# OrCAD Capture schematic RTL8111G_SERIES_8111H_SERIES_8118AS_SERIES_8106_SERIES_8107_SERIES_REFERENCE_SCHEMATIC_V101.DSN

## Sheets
1 P06. Change Note: title: RTL81Gseries_81Hseries_8118ASseries_8106series_8107series 32 Pin Reference Schematic: Change Note; rev: A1; company: Realtek Semiconductor Corp.; note: RTL81Gseries_81Hseries_8118ASseries_8106series_8107series 32 Pin Reference Schematic; note: No.2, Innovation Road II, Hsinchu Science Park, Hsinchu 300, Taiwan
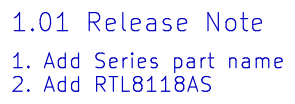
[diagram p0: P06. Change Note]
2 P01. Index: title: RTL81Gseries_81Hseries_8118ASseries_8106series_8107series 32 Pin Reference Schematic: Index
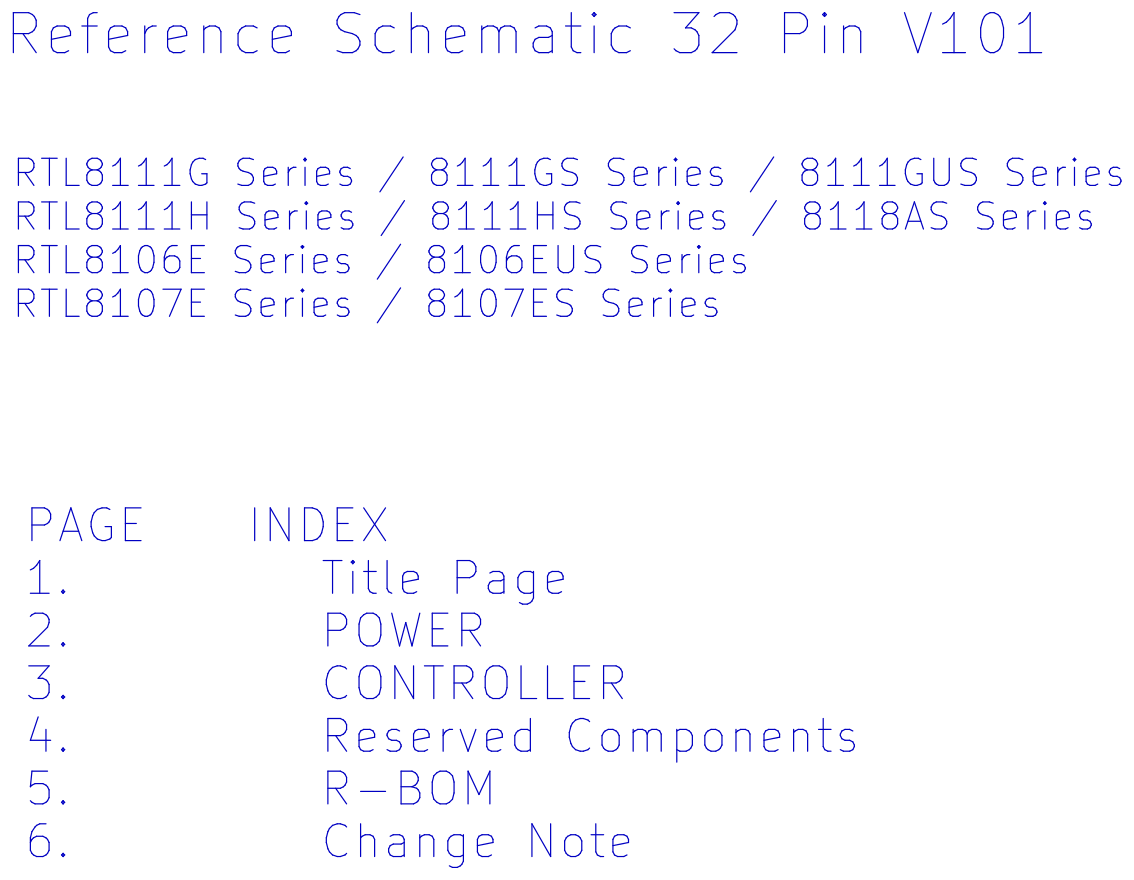
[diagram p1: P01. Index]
3 P02. POWER: size A3; title: RTL81Gseries_81Hseries_8118ASseries_8106series_8107series 32 Pin Reference Schematic : Power
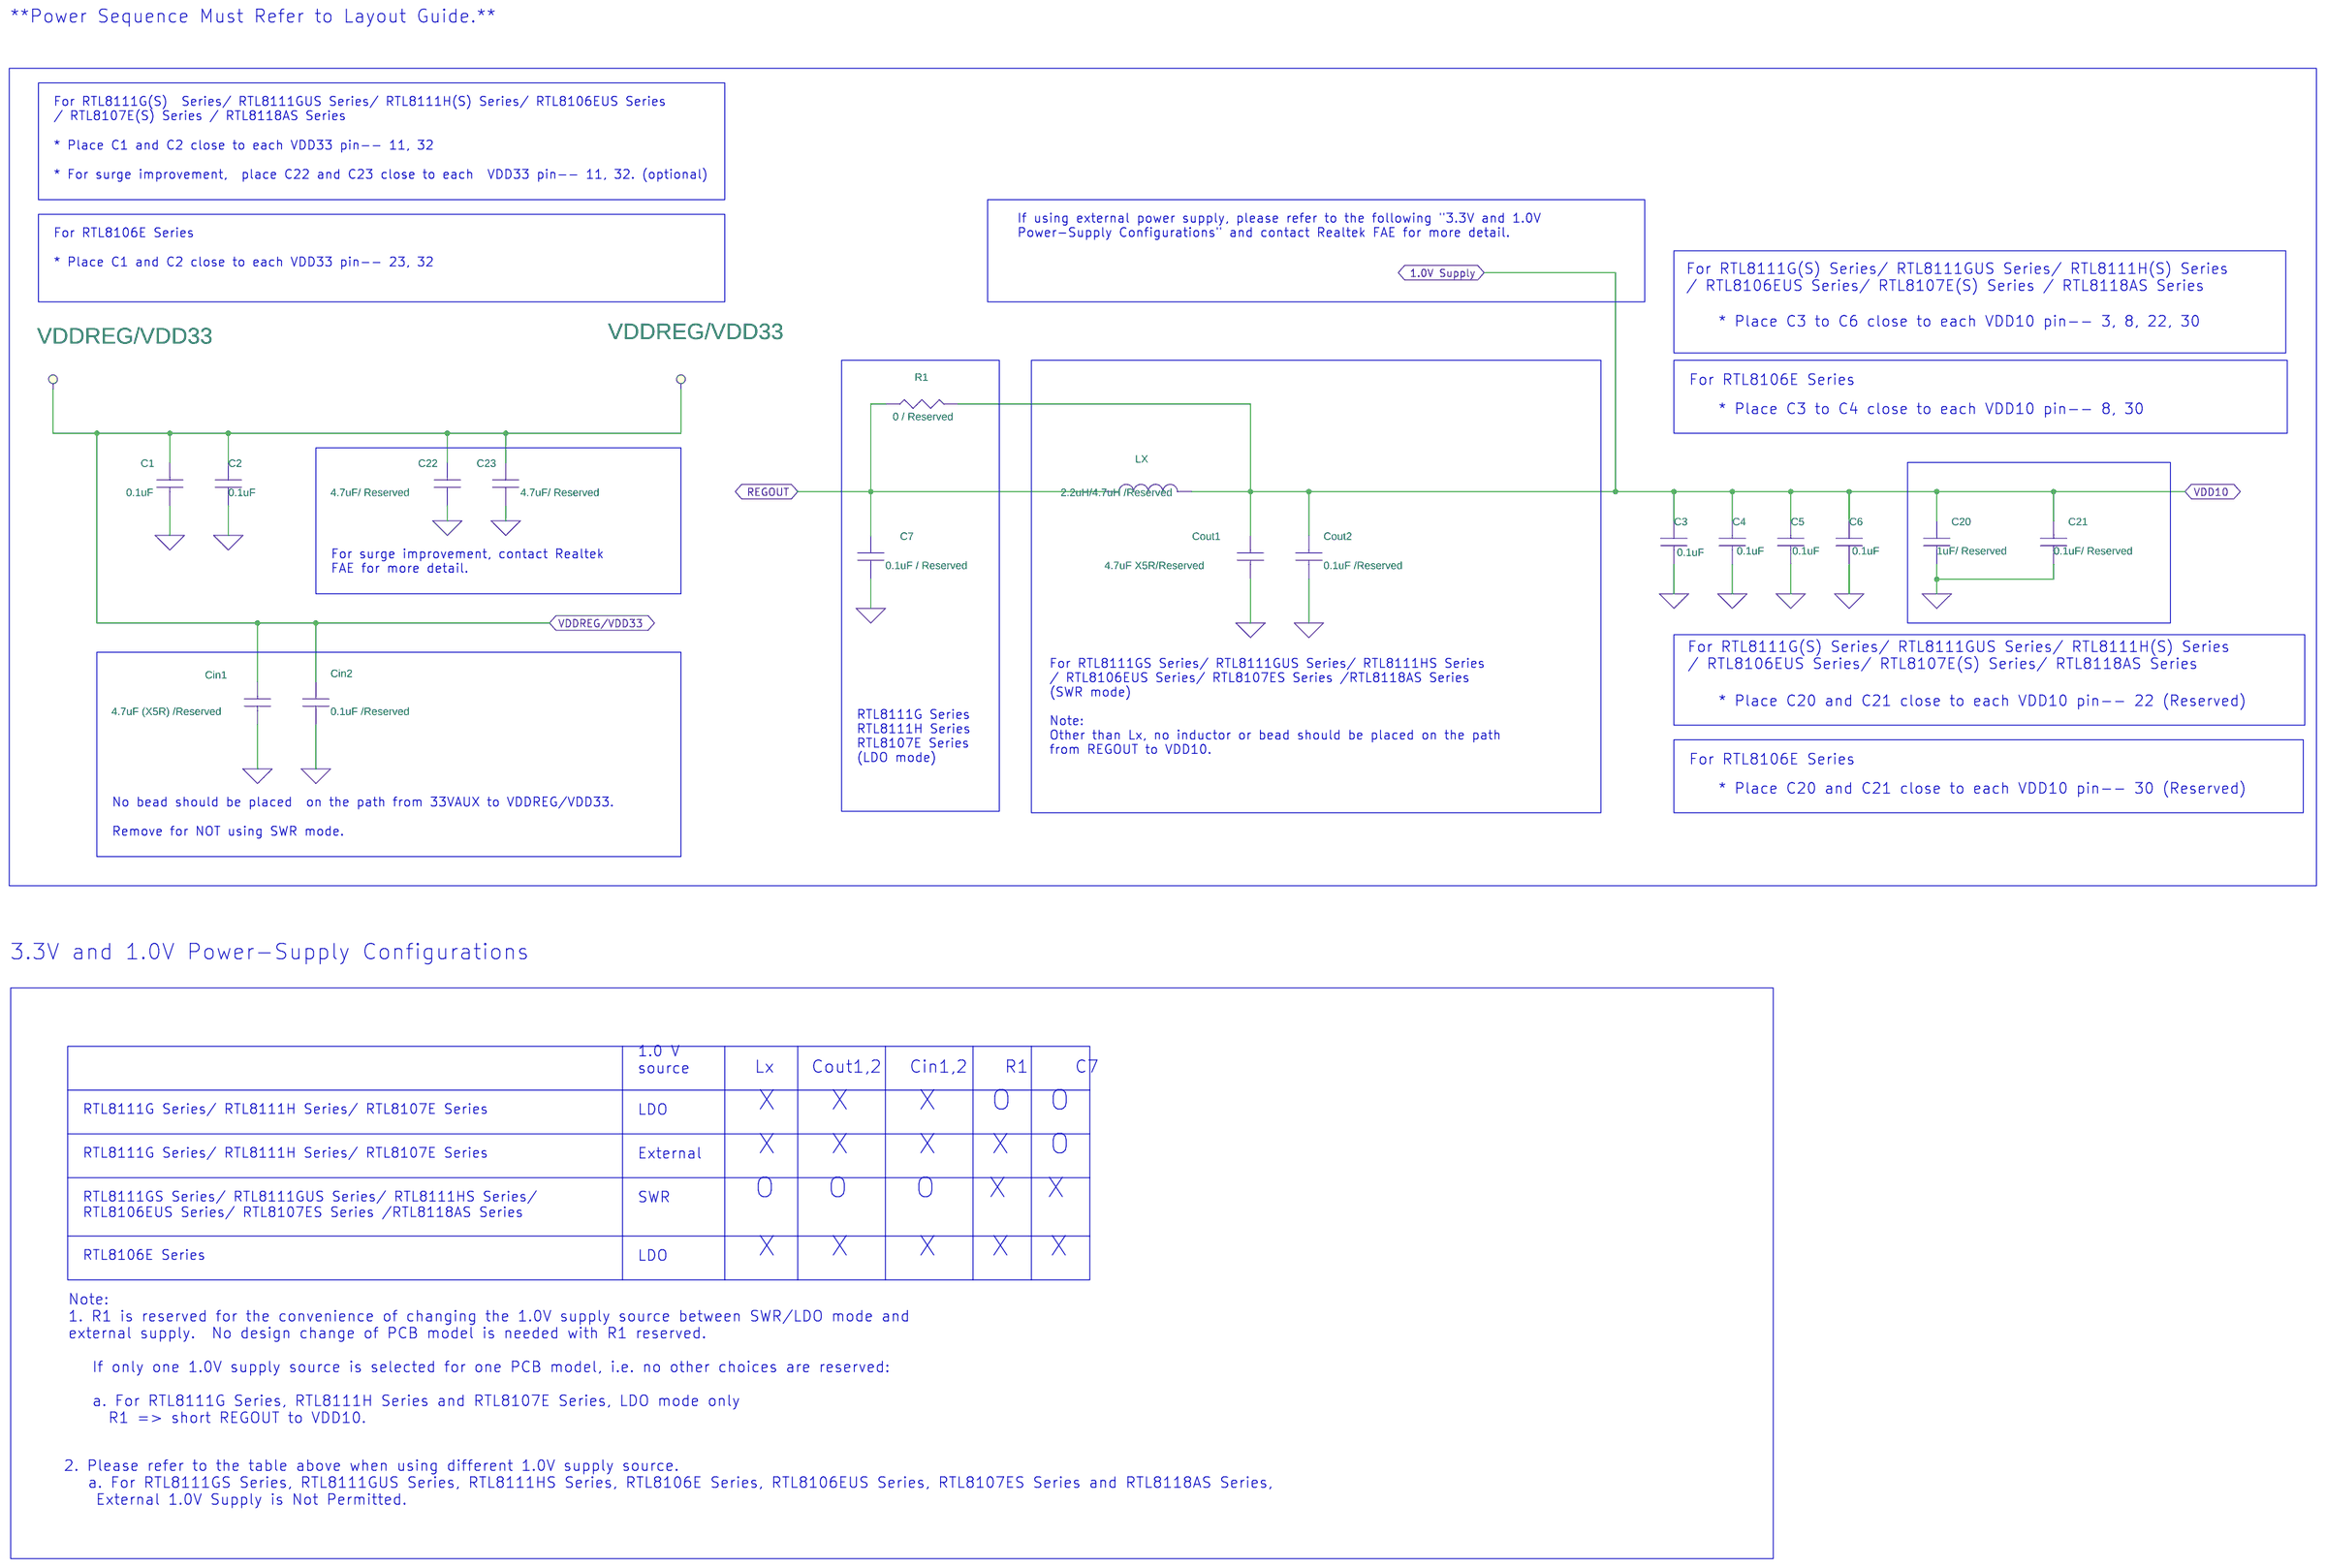
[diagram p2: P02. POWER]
4 P03. CONTROLLER: size A3; title: RTL81Gseries_81Hseries_8118ASseries_8106series_8107series 32 Pin Reference Schematic: Controller
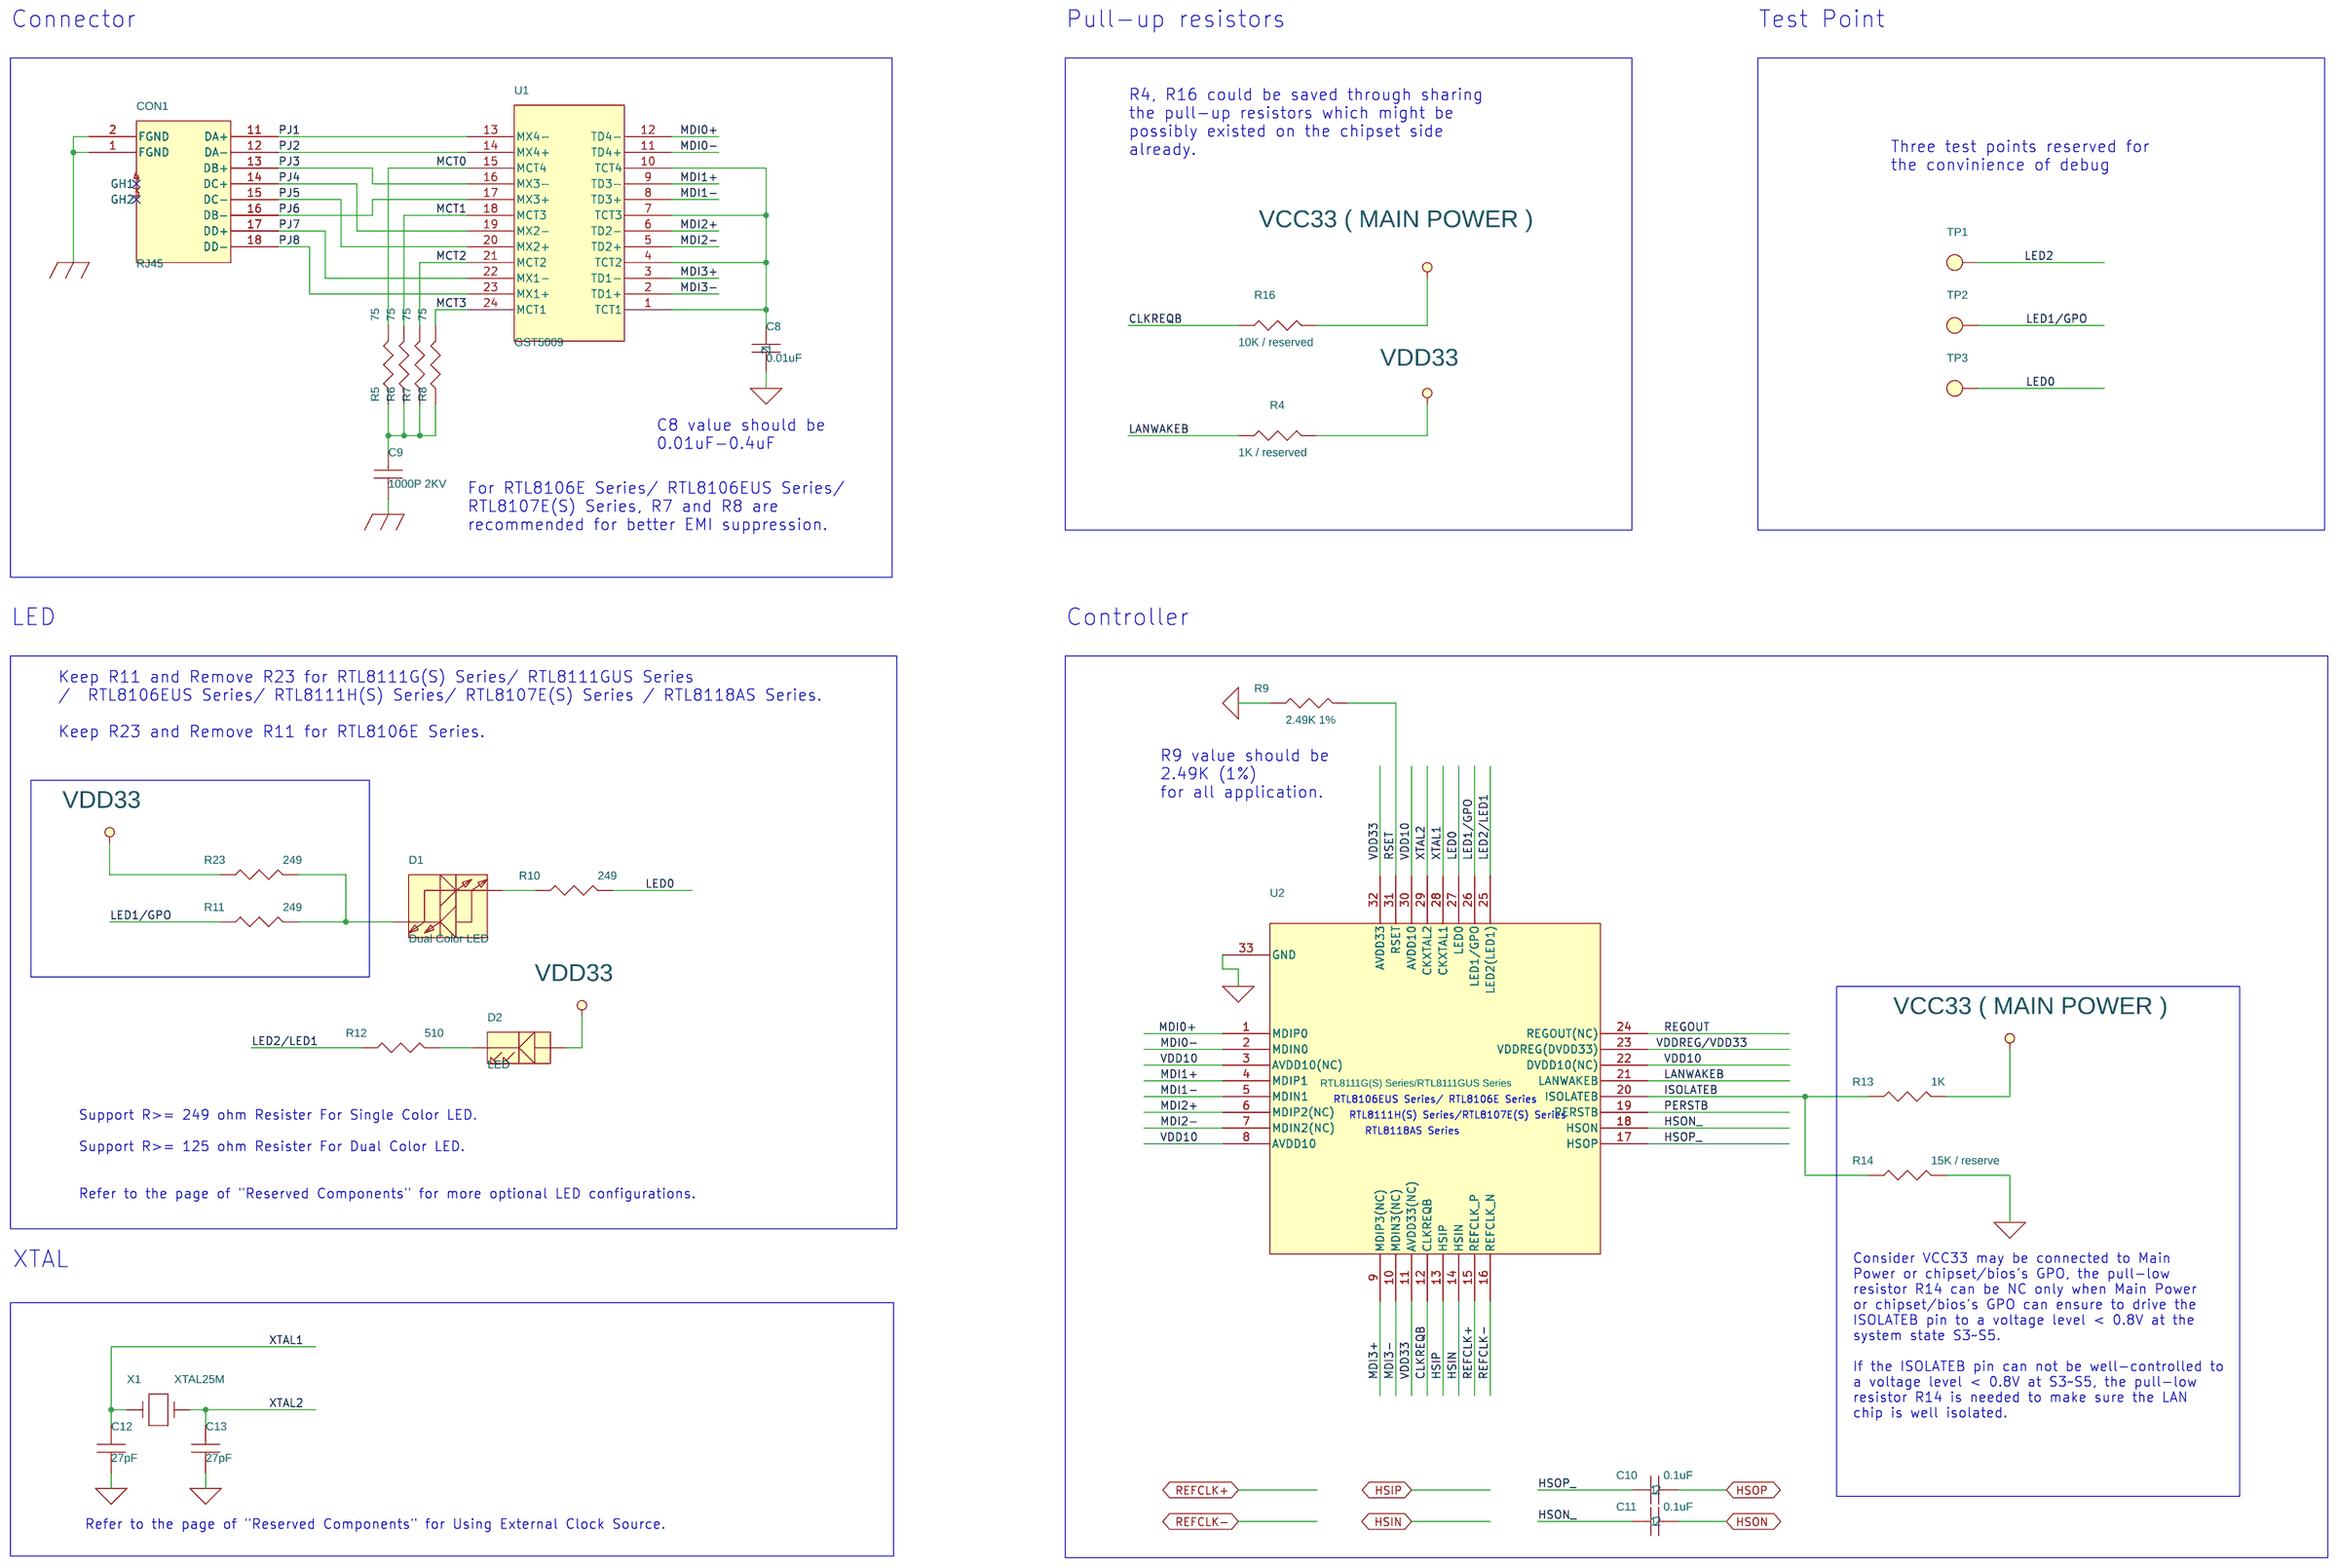
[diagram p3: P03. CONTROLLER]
5 P04. Reserved Components: size A3; title: RTL81Gseries_81Hseries_8118ASseries_8106series_8107series 32 Pin Reference Schematic:Reserved Components
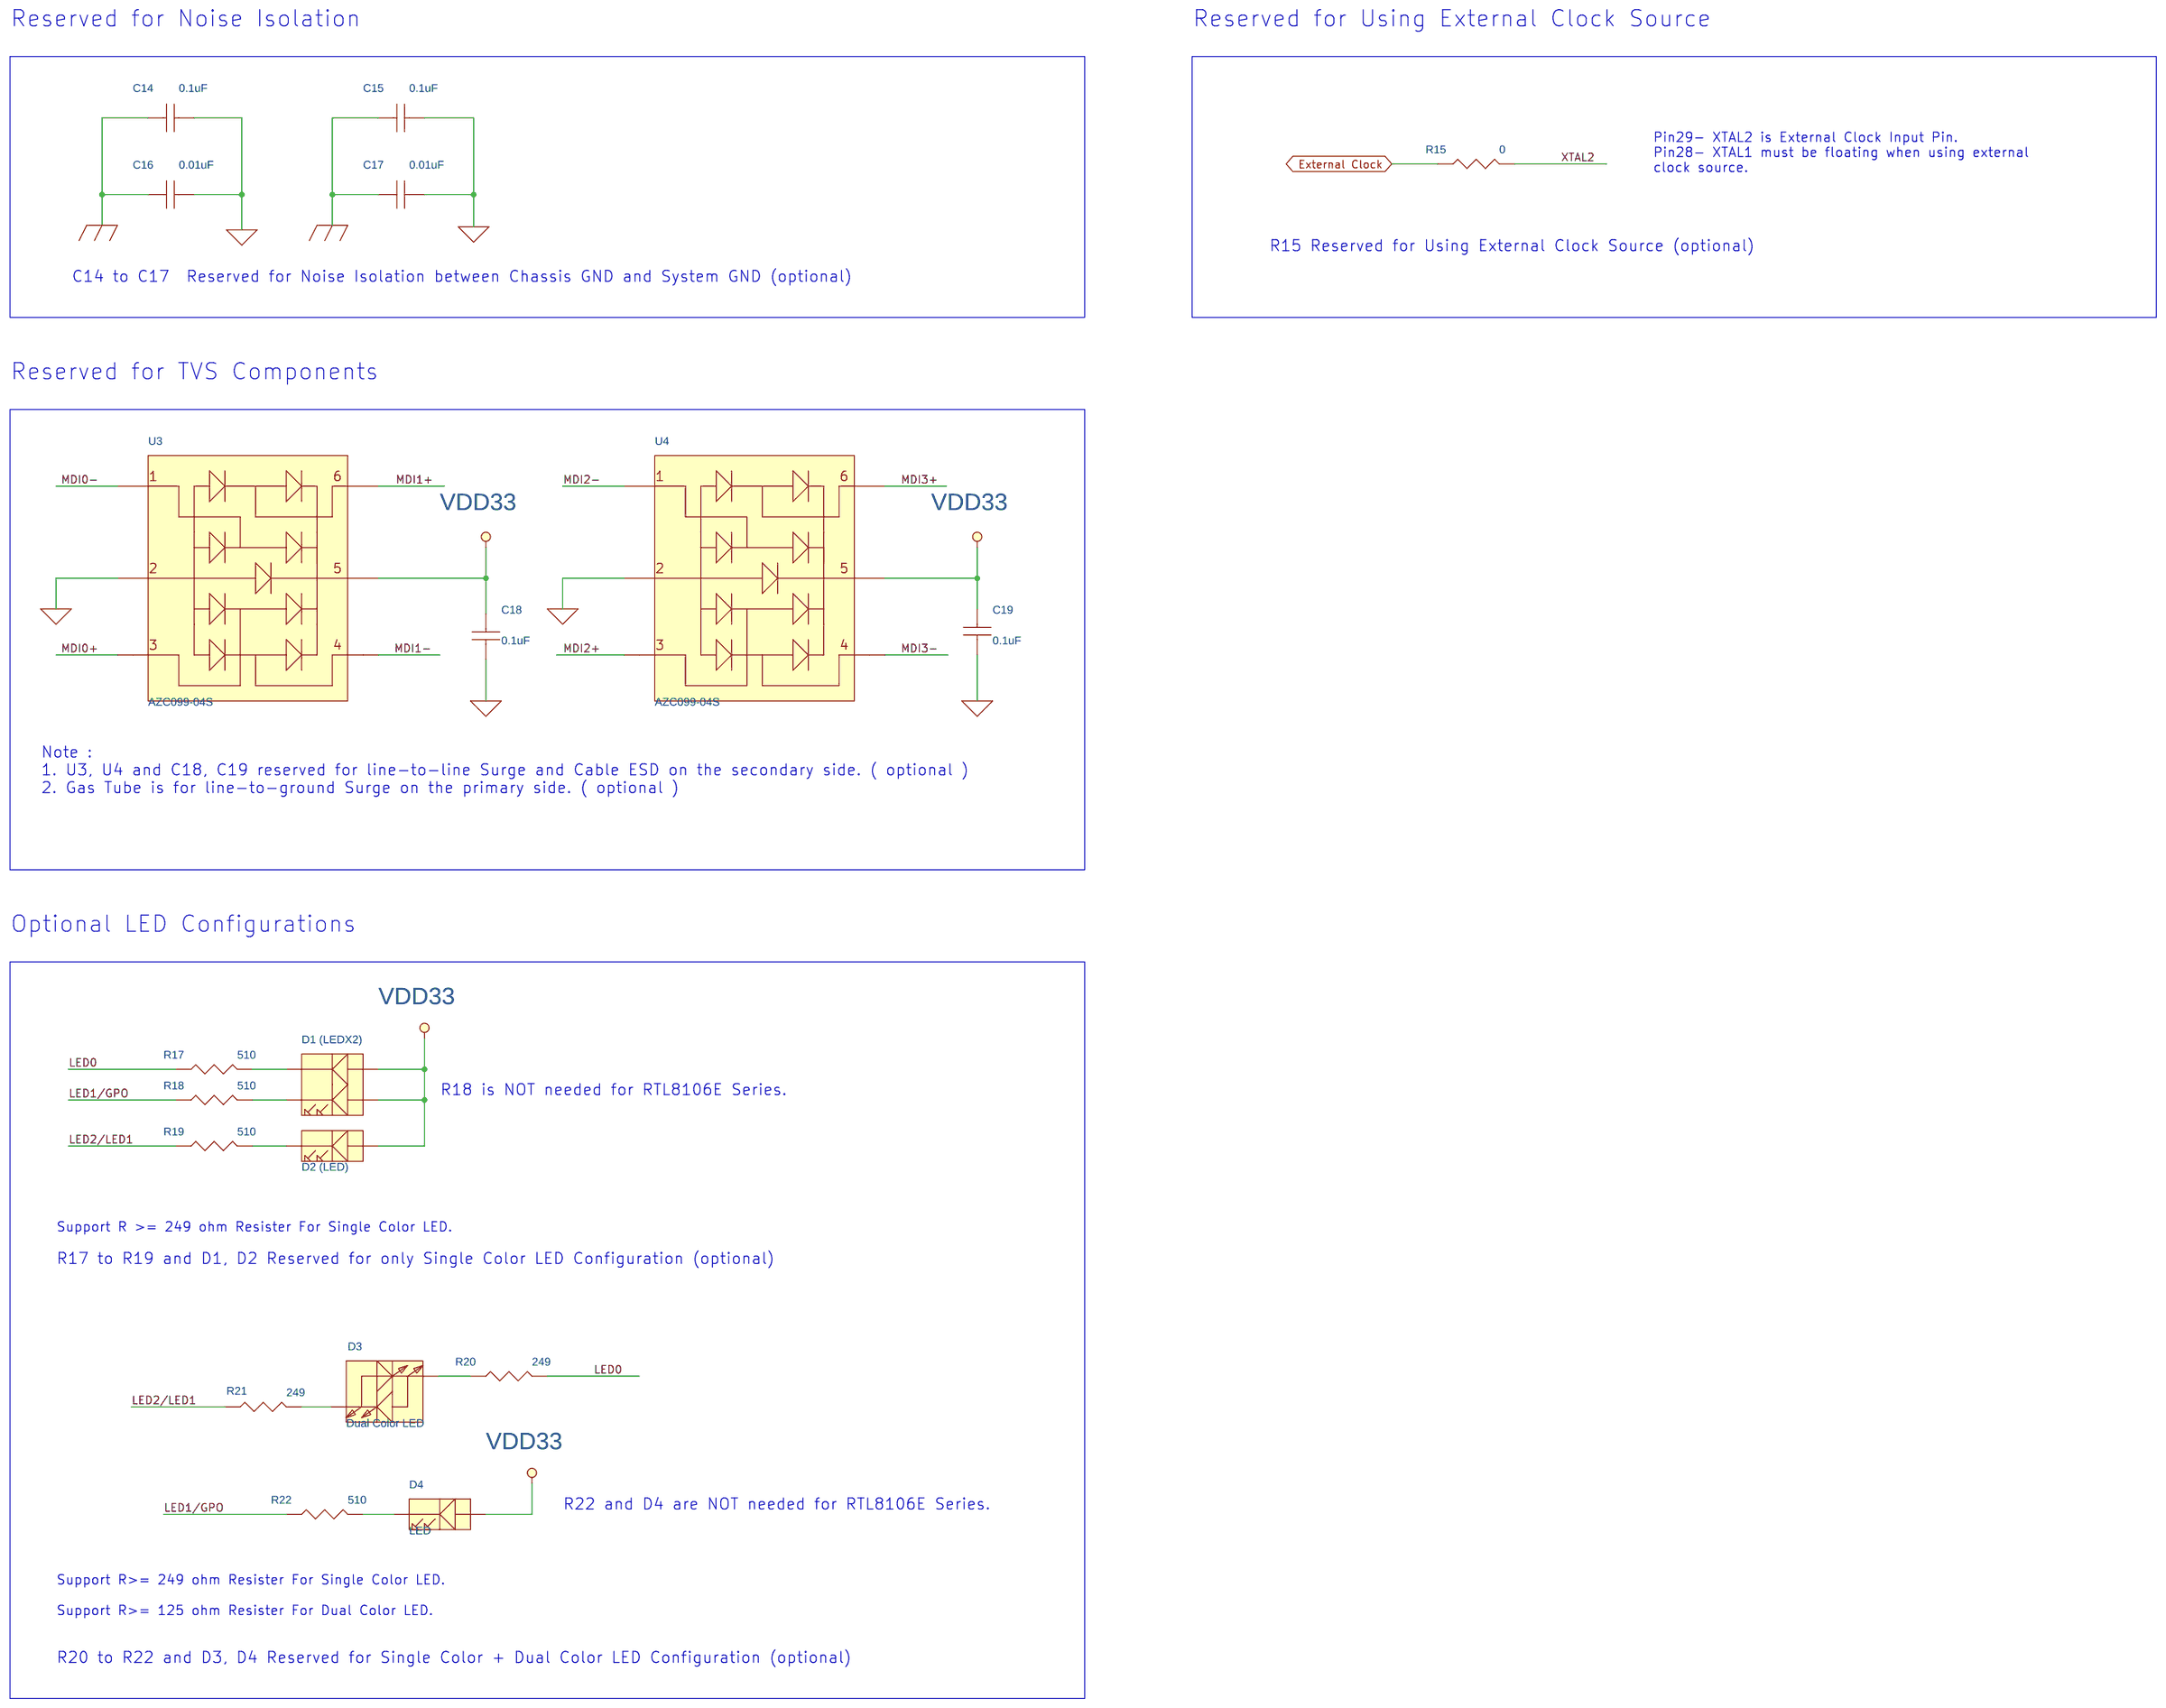
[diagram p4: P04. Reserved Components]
6 P05. R-BOM: title: RTL81Gseries_81Hseries_8118ASseries_8106series_8107series 32 Pin Reference Schematic: Bill of Materials
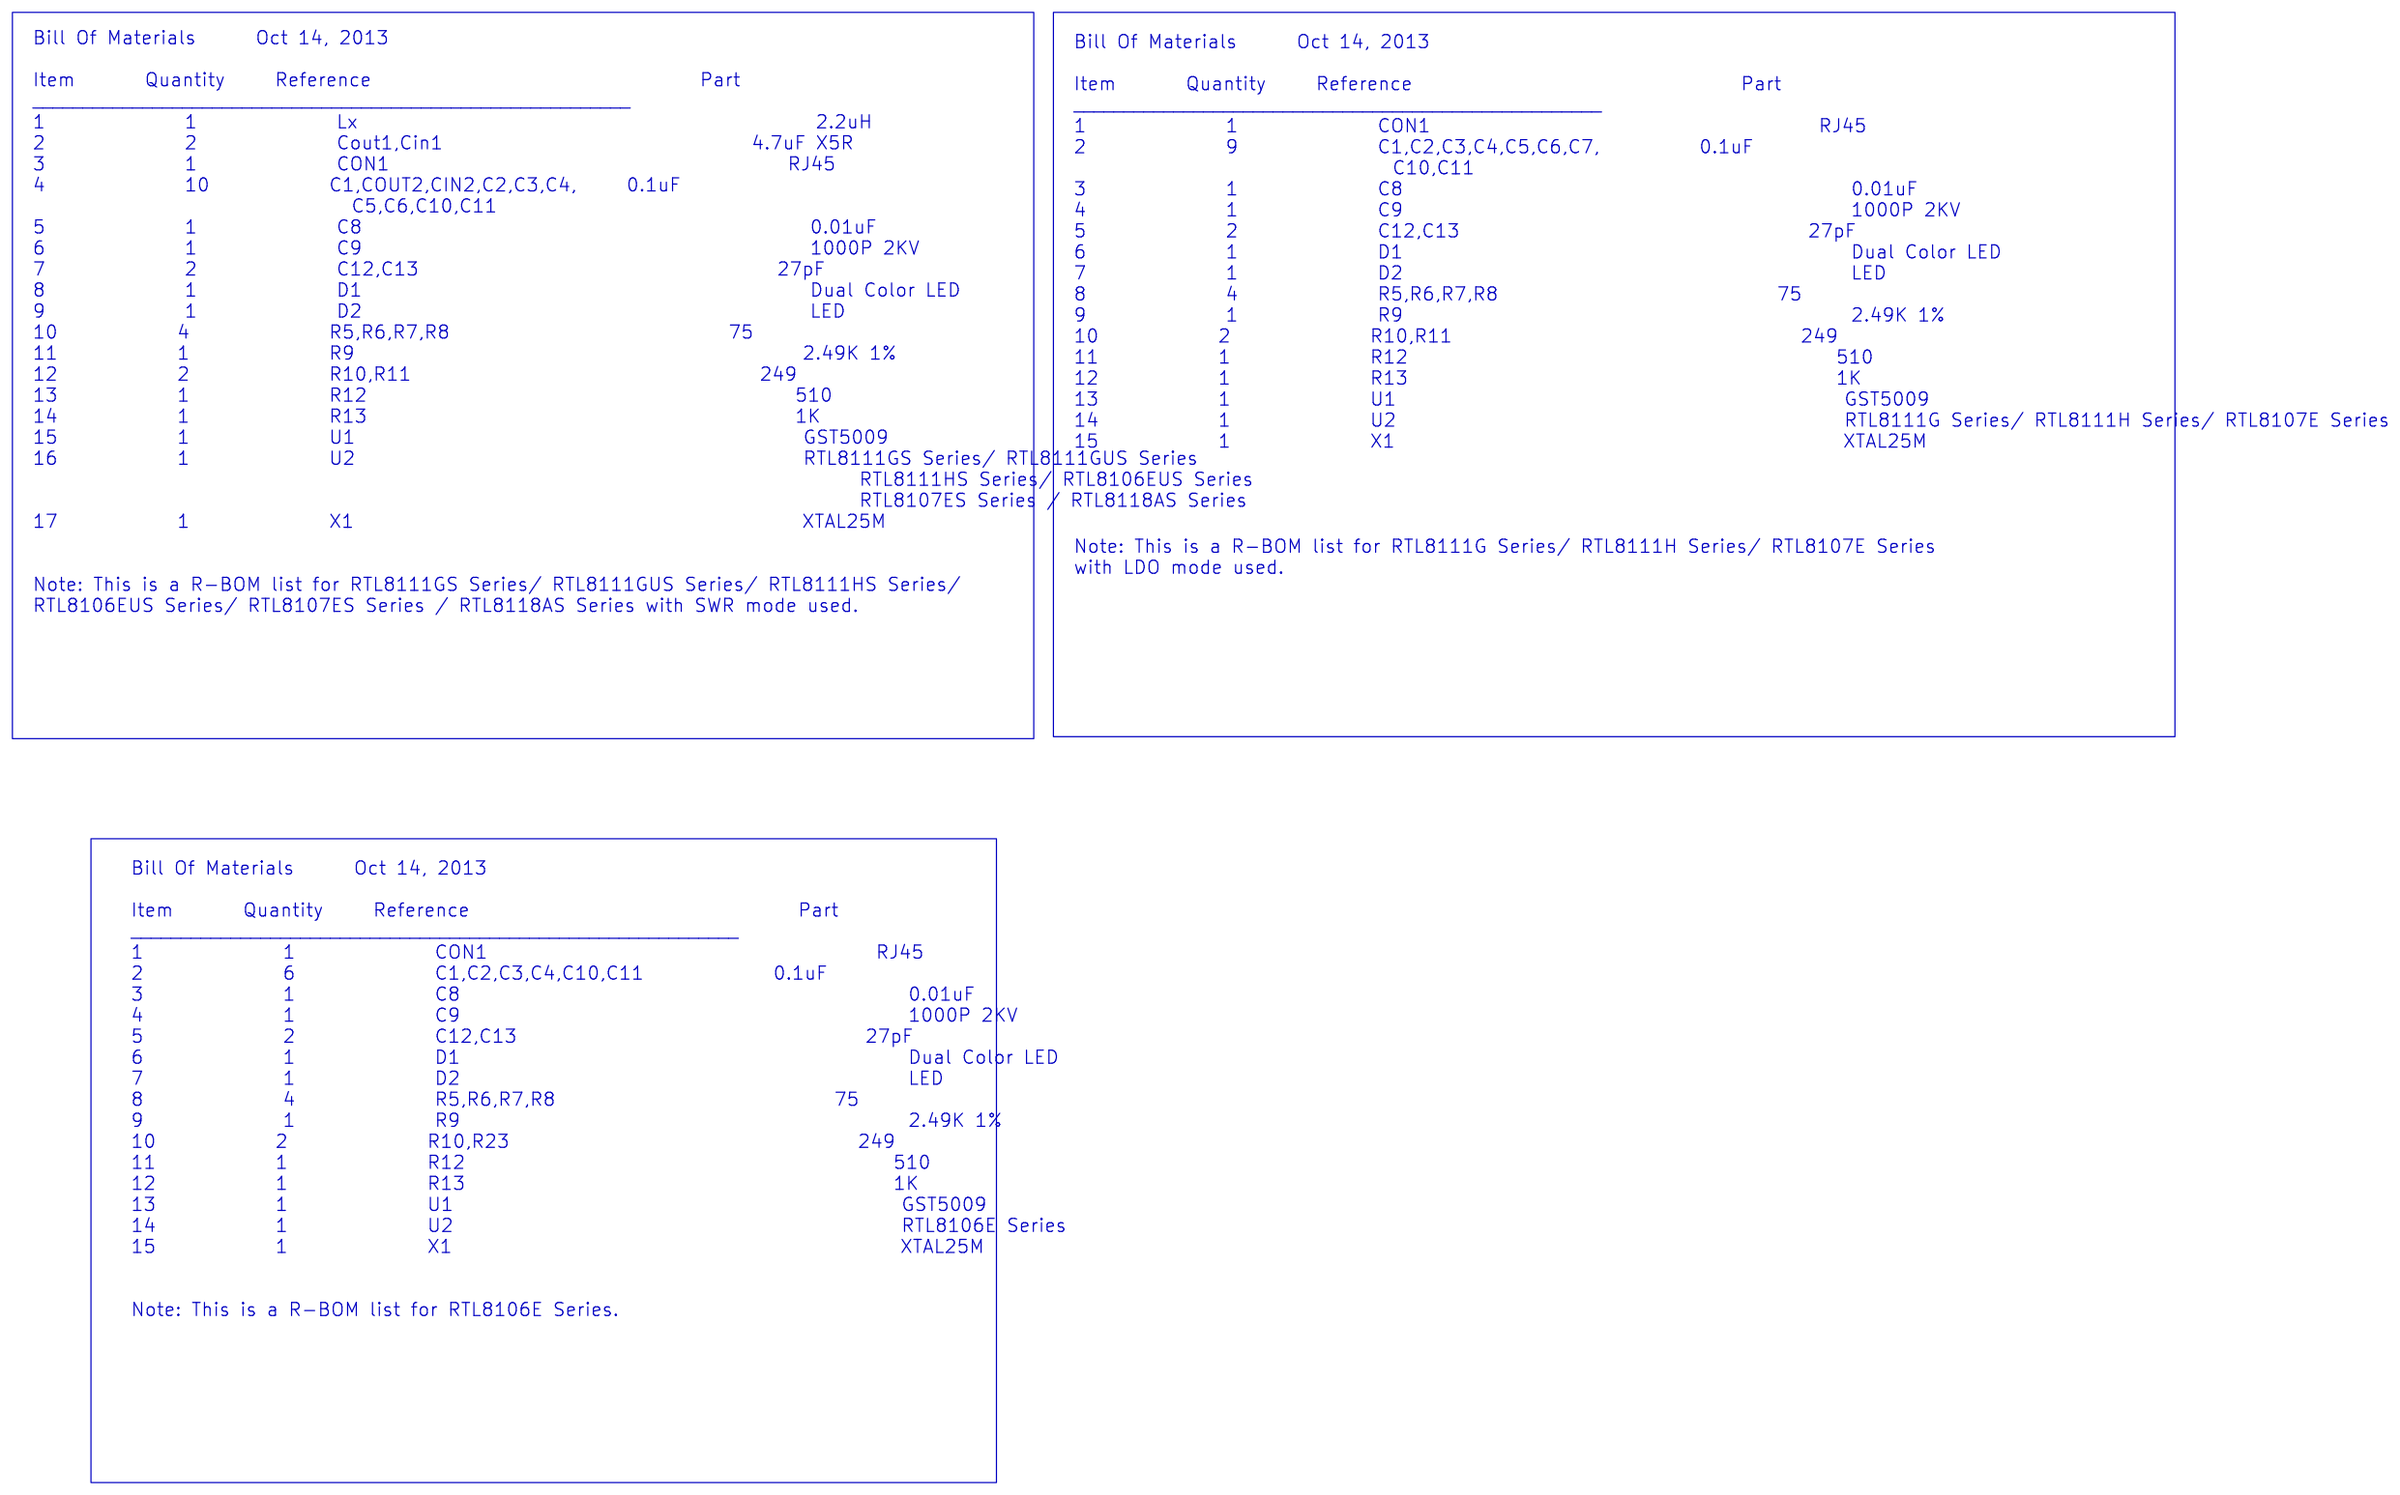
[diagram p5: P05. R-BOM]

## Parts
sheet P02. POWER
C1  0.1uF  [C0402C]
C2  0.1uF  [C0402C]
C3  0.1uF  [C0402C]
C4  0.1uF  [C0402C]
C5  0.1uF  [C0402C]
C6  0.1uF  [C0402C]
C7  0.1uF / Reserved  [C0402C]
C20  1uF/ Reserved  [C0402C]
C21  0.1uF/ Reserved  [C0402C]
C22  4.7uF/ Reserved  [C1206C]
C23  4.7uF/ Reserved  [C1206C]
Cin1  4.7uF (X5R) /Reserved  [C1206C]
Cin2  0.1uF /Reserved  [C0402C]
Cout1  4.7uF X5R/Reserved  [C0805C]
Cout2  0.1uF /Reserved  [C0402C]
LX  2.2uH/4.7uH /Reserved  [L\5X5\3.15]
R1  0 / Reserved  [R0603R]
sheet P03. CONTROLLER
C8  0.01uF  [C0402C]
C9  1000P 2KV  [C1206C]
C10  0.1uF
C11  0.1uF
C12  27pF  [C0402C]
C13  27pF  [C0402C]
CON1  RJ45  [RJ45S1X1]
D1  Dual Color LED  [LED2X2]
D2  LED  [LED]
R4  1K / reserved  [R0402R]
R5  75  [R0402R]
R6  75  [R0402R]
R7  75  [R0402R]
R8  75  [R0402R]
R9  2.49K 1%  [R0402R]
R10  249  [R0402R]
R11  249  [R0402R]
R12  510  [R0402R]
R13  1K  [R0402R]
R14  15K / reserve  [R0402R]
R16  10K / reserved  [R0402R]
R23  249  [R0402R]
TP1  TEST POINT
TP2  TEST POINT
TP3  TEST POINT
U1  GST5009  [GST5009-LFE9249-R]
U2  RTL8111G(S) Series/RTL8111GUS Series  [QFN6x6-48]
X1  XTAL25M  [XTAL]
sheet P04. Reserved Components
C14  0.1uF  [C0402C]
C15  0.1uF  [C0402C]
C16  0.01uF  [C0402C]
C17  0.01uF  [C0402C]
C18  0.1uF  [C0402C]
C19  0.1uF  [C0402C]
D1 (LEDX2)  LEDx2  [LED2X2]
D2 (LED)  LED  [LED]
D3  Dual Color LED  [LED2X2]
D4  LED  [LED]
R15  0  [R0402R]
R17  510  [R0402R]
R18  510  [R0402R]
R19  510  [R0402R]
R20  249  [R0402R]
R21  249  [R0402R]
R22  510  [R0402R]
U3  AZC099-04S  [SOT23-6L]
U4  AZC099-04S  [SOT23-6L]

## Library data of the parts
C1 = CAPACITOR_NON-POL_0: ROOM: 33vaux
C2 C9 C12-C17 C22 C23 Cin1 Cin2 = CAPACITOR_NON-POL_0
C3-C5 = CAPACITOR_NON-POL_0: ROOM: c_15
C6 C7 C20 C21 Cout1 Cout2 = CAPACITOR_NON-POL_0: ROOM: vdd18
LX = INDUCTOR_0: ROOM: vdd18
R1 R4-R23 = R
C8 = CAP_NP
C10 = CAP_NP_2
C11 C18 C19 = CAP_NP_1
CON1 = RJ45_2
D1 D3 = LED_2
D2 D2 (LED) D4 = LED_3
TP1-TP3 = TEST_POINT
U1 = H5007
U2 = RL5877_66
X1 = CRYSTAL_0
D1 (LEDX2) = LED_1
U3 U4 = 9346_5

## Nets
1.0V Supply: C3.1 C4.1 C5.1 C6.1 C20.1 C21.1 Cout1.1 Cout2.1 LX.2 R1.2
DGND: C1.2 C2.2 C3.2 C4.2 C5.2 C6.2 C7.2 C8.2 C12.2 C13.2 C14.2 C15.2 C16.2 C17.2 C18.2 C19.2 C20.2 C21.2 C22.2 C23.2 Cin1.2 Cin2.2 Cout1.2 Cout2.2 R9.1 R14.2 U2.33(GND) U3.2 U4.2
VCC33 ( Main Power ): R13.2 R16.2
VDD10: U2.3(AVDD10(NC)) U2.8(AVDD10) U2.22(DVDD10(NC)) U2.30(AVDD10)
VDD33: C1.1 C2.1 C18.1 C19.1 C22.1 C23.1 Cin1.1 Cin2.1 D1 (LEDX2).1 D1 (LEDX2).2 D2.1 D2 (LED).1 D4.1 R4.2 R23.1 U2.11(AVDD33(NC)) U2.32(AVDD33) U3.5 U4.5
VDDREG/VDD33: U2.23(VDDREG(DVDD33))
CLKREQB: R16.1 U2.12(CLKREQB)
External Clock: R15.1
FGND: C9.2 C14.1 C15.1 C16.1 C17.1 CON1.1(FGND) CON1.2(FGND)
HSIN: U2.14(HSIN)
HSIP: U2.13(HSIP)
HSON: C11.2
HSON_: C11.1 U2.18(HSON)
HSOP: C10.2
HSOP_: C10.1 U2.17(HSOP)
ISOLATEB: R13.1 R14.1 U2.20(ISOLATEB)
LANWAKEB: R4.1 U2.21(LANWAKEB)
LED0: R10.2 TP3.1 U2.27(LED0)
LED0 (page P04. Reserved Components): R17.1 R20.2
LED1/GPO: R11.1 TP2.1 U2.26(LED1/GPO)
LED1/GPO (page P04. Reserved Components): R18.1 R22.1
LED2: TP1.1
LED2/LED1: R12.1 U2.25(LED2(LED1))
LED2/LED1 (page P04. Reserved Components): R19.1 R21.1
MCT0: R5.2 U1.15(MCT4)
MCT1: R6.2 U1.18(MCT3)
MCT2: R7.2 U1.21(MCT2)
MCT3: R8.2 U1.24(MCT1)
MDI0+: U1.12(TD4-) U2.1(MDIP0)
MDI0+ (page P04. Reserved Components): U3.3
MDI0-: U1.11(TD4+) U2.2(MDIN0)
MDI0- (page P04. Reserved Components): U3.1
MDI1+: U1.9(TD3-) U2.4(MDIP1)
MDI1+ (page P04. Reserved Components): U3.6
MDI1-: U1.8(TD3+) U2.5(MDIN1)
MDI1- (page P04. Reserved Components): U3.4
MDI2+: U1.6(TD2-) U2.6(MDIP2(NC))
MDI2+ (page P04. Reserved Components): U4.3
MDI2-: U1.5(TD2+) U2.7(MDIN2(NC))
MDI2- (page P04. Reserved Components): U4.1
MDI3+: U1.3(TD1-) U2.9(MDIP3(NC))
MDI3+ (page P04. Reserved Components): U4.6
MDI3-: U1.2(TD1+) U2.10(MDIN3(NC))
MDI3- (page P04. Reserved Components): U4.4
PERSTB: U2.19(PERSTB)
PJ1: CON1.11(DA+) U1.13(MX4-)
PJ2: CON1.12(DA-) U1.14(MX4+)
PJ3: CON1.13(DB+) U1.16(MX3-)
PJ4: CON1.14(DC+) U1.19(MX2-)
PJ5: CON1.15(DC-) U1.20(MX2+)
PJ6: CON1.16(DB-) U1.17(MX3+)
PJ7: CON1.17(DD+) U1.22(MX1-)
PJ8: CON1.18(DD-) U1.23(MX1+)
REFCLK+: U2.15(REFCLK_P)
REFCLK-: U2.16(REFCLK_N)
REGOUT: C7.1 LX.1 R1.1
REGOUT (page P03. CONTROLLER): U2.24(REGOUT(NC))
RSET: R9.2 U2.31(RSET)
XTAL1: C12.1 U2.28(CKXTAL1) X1.1
XTAL2: C13.1 U2.29(CKXTAL2) X1.2
XTAL2 (page P04. Reserved Components): R15.2
N48283: C9.1 R5.1 R6.1 R7.1 R8.1
N17380918: C8.1 U1.1(TCT1) U1.4(TCT2) U1.7(TCT3) U1.10(TCT4)
N19422524: D1.2 R11.2 R23.2
N19450336: D2.2 R12.2
N20002596: D1 (LEDX2).3 R17.2
N20002600: D1 (LEDX2).4 R18.2
N20002614: D2 (LED).2 R19.2
N20007964: D4.2 R22.2
N20008009: D3.1 R20.1
N20008023: D3.2 R21.2
N20277785: D1.1 R10.1

Not connected (* = marked no-connect by the designer): CON1 3(GH2)* 4(GH1)*

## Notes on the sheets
sheet 1
- 1.01 Release Note
- 1. Add Series part name
  2. Add RTL8118AS
sheet 2
- Reference Schematic 32 Pin V101
- RTL8111G Series / 8111GS Series / 8111GUS Series
  RTL8111H Series / 8111HS Series / 8118AS Series
  RTL8106E Series / 8106EUS Series
  RTL8107E Series / 8107ES Series
- PAGE    INDEX
  1.          Title Page
  2.          POWER
  3.          CONTROLLER
  4.          Reserved Components
  5.          R-BOM
  6.          Change Note
sheet 3
- **Power Sequence Must Refer to Layout Guide.**
- For RTL8111G(S)  Series/ RTL8111GUS Series/ RTL8111H(S) Series/ RTL8106EUS Series
  / RTL8107E(S) Series / RTL8118AS Series
- * Place C1 and C2 close to each VDD33 pin-- 11, 32
- * For surge improvement,  place C22 and C23 close to each  VDD33 pin-- 11, 32. (optional)
- If using external power supply, please refer to the following "3.3V and 1.0V
  Power-Supply Configurations" and contact Realtek FAE for more detail.
- For RTL8106E Series
- * Place C1 and C2 close to each VDD33 pin-- 23, 32
- For RTL8111G(S) Series/ RTL8111GUS Series/ RTL8111H(S) Series
  / RTL8106EUS Series/ RTL8107E(S) Series / RTL8118AS Series
- * Place C3 to C6 close to each VDD10 pin-- 3, 8, 22, 30
- For RTL8106E Series
- * Place C3 to C4 close to each VDD10 pin-- 8, 30
- For surge improvement, contact Realtek
  FAE for more detail.
- For RTL8111G(S) Series/ RTL8111GUS Series/ RTL8111H(S) Series
  / RTL8106EUS Series/ RTL8107E(S) Series/ RTL8118AS Series
- For RTL8111GS Series/ RTL8111GUS Series/ RTL8111HS Series
  / RTL8106EUS Series/ RTL8107ES Series /RTL8118AS Series
  (SWR mode)
  Note:
  Other than Lx, no inductor or bead should be placed on the path
  from REGOUT to VDD10.
- * Place C20 and C21 close to each VDD10 pin-- 22 (Reserved)
- RTL8111G Series
  RTL8111H Series
  RTL8107E Series
  (LDO mode)
- For RTL8106E Series
- * Place C20 and C21 close to each VDD10 pin-- 30 (Reserved)
- No bead should be placed  on the path from 33VAUX to VDDREG/VDD33.
- Remove for NOT using SWR mode.
- 3.3V and 1.0V Power-Supply Configurations
- 1.0 V
  source
- Lx    Cout1,2   Cin1,2    R1     C7
- X
- X
- X
- O
- O
- RTL8111G Series/ RTL8111H Series/ RTL8107E Series
- LDO
- X
- X
- X
- X
- O
- RTL8111G Series/ RTL8111H Series/ RTL8107E Series
- External
- O
- O
- O
- X
- X
- RTL8111GS Series/ RTL8111GUS Series/ RTL8111HS Series/
  RTL8106EUS Series/ RTL8107ES Series /RTL8118AS Series
- SWR
- X
- X
- X
- X
- X
- RTL8106E Series
- LDO
- Note:
  1. R1 is reserved for the convenience of changing the 1.0V supply source between SWR/LDO mode and
  external supply.  No design change of PCB model is needed with R1 reserved.
     If only one 1.0V supply source is selected for one PCB model, i.e. no other choices are reserved:
     a. For RTL8111G Series, RTL8111H Series and RTL8107E Series, LDO mode only
       R1 => short REGOUT to VDD10.
- 2. Please refer to the table above when using different 1.0V supply source.
     a. For RTL8111GS Series, RTL8111GUS Series, RTL8111HS Series, RTL8106E Series, RTL8106EUS Series, RTL8107ES Series and RTL8118AS Series,
      External 1.0V Supply is Not Permitted.
sheet 4
- Connector
- Pull-up resistors
- Test Point
- R4, R16 could be saved through sharing
  the pull-up resistors which might be
  possibly existed on the chipset side
  already.
- Three test points reserved for
  the convinience of debug
- C8 value should be
  0.01uF-0.4uF
- For RTL8106E Series/ RTL8106EUS Series/
  RTL8107E(S) Series, R7 and R8 are
  recommended for better EMI suppression.
- LED
- Controller
- Keep R11 and Remove R23 for RTL8111G(S) Series/ RTL8111GUS Series
  /  RTL8106EUS Series/ RTL8111H(S) Series/ RTL8107E(S) Series / RTL8118AS Series.
  Keep R23 and Remove R11 for RTL8106E Series.
- R9 value should be
  2.49K (1%)
  for all application.
- Support R>= 249 ohm Resister For Single Color LED.
- RTL8106EUS Series/ RTL8106E Series
- RTL8111H(S) Series/RTL8107E(S) Series
- RTL8118AS Series
- Support R>= 125 ohm Resister For Dual Color LED.
- Refer to the page of "Reserved Components" for more optional LED configurations.
- XTAL
- Consider VCC33 may be connected to Main
  Power or chipset/bios's GPO, the pull-low
  resistor R14 can be NC only when Main Power
  or chipset/bios's GPO can ensure to drive the
  ISOLATEB pin to a voltage level < 0.8V at the
  system state S3~S5.
  If the ISOLATEB pin can not be well-controlled to
  a voltage level < 0.8V at S3~S5, the pull-low
  resistor R14 is needed to make sure the LAN
  chip is well isolated.
- Refer to the page of "Reserved Components" for Using External Clock Source.
sheet 5
- Reserved for Noise Isolation
- Reserved for Using External Clock Source
- Pin29- XTAL2 is External Clock Input Pin.
  Pin28- XTAL1 must be floating when using external
  clock source.
- R15 Reserved for Using External Clock Source (optional)
- C14 to C17  Reserved for Noise Isolation between Chassis GND and System GND (optional)
- Reserved for TVS Components
- Note :
  1. U3, U4 and C18, C19 reserved for line-to-line Surge and Cable ESD on the secondary side. ( optional )
  2. Gas Tube is for line-to-ground Surge on the primary side. ( optional )
- Optional LED Configurations
- R18 is NOT needed for RTL8106E Series.
- Support R >= 249 ohm Resister For Single Color LED.
- R17 to R19 and D1, D2 Reserved for only Single Color LED Configuration (optional)
- R22 and D4 are NOT needed for RTL8106E Series.
- Support R>= 249 ohm Resister For Single Color LED.
- Support R>= 125 ohm Resister For Dual Color LED.
- R20 to R22 and D3, D4 Reserved for Single Color + Dual Color LED Configuration (optional)
sheet 6
- Bill Of Materials      Oct 14, 2013
  Item       Quantity     Reference                                 Part
  ____________________________________________________________
  1              1              Lx                                              2.2uH
  2              2              Cout1,Cin1                               4.7uF X5R
  3              1              CON1                                        RJ45
  4              10            C1,COUT2,CIN2,C2,C3,C4,     0.1uF
                                  C5,C6,C10,C11
  5              1              C8                                             0.01uF
  6              1              C9                                             1000P 2KV
  7              2              C12,C13                                    27pF
  8              1              D1                                             Dual Color LED
  9              1              D2                                             LED
  10            4              R5,R6,R7,R8                            75
  11            1              R9                                             2.49K 1%
  12            2              R10,R11                                   249
  13            1              R12                                           510
  14            1              R13                                           1K
  15            1              U1                                             GST5009
  16            1              U2                                             RTL8111GS Series/ RTL8111GUS Series
                                                                                     RTL8111HS Series/ RTL8106EUS Series
                                                                                     RTL8107ES Series / RTL8118AS Series
  17            1              X1                                             XTAL25M
  Note: This is a R-BOM list for RTL8111GS Series/ RTL8111GUS Series/ RTL8111HS Series/
  RTL8106EUS Series/ RTL8107ES Series / RTL8118AS Series with SWR mode used.
- Bill Of Materials      Oct 14, 2013
  Item       Quantity     Reference                                 Part
  _____________________________________________________
  1              1              CON1                                       RJ45
  2              9              C1,C2,C3,C4,C5,C6,C7,          0.1uF
                                  C10,C11
  3              1              C8                                             0.01uF
  4              1              C9                                             1000P 2KV
  5              2              C12,C13                                   27pF
  6              1              D1                                             Dual Color LED
  7              1              D2                                             LED
  8              4              R5,R6,R7,R8                            75
  9              1              R9                                             2.49K 1%
  10            2              R10,R11                                   249
  11            1              R12                                           510
  12            1              R13                                           1K
  13            1              U1                                             GST5009
  14            1              U2                                             RTL8111G Series/ RTL8111H Series/ RTL8107E Series
  15            1              X1                                             XTAL25M
  Note: This is a R-BOM list for RTL8111G Series/ RTL8111H Series/ RTL8107E Series
  with LDO mode used.
- Bill Of Materials      Oct 14, 2013
  Item       Quantity     Reference                                 Part
  _____________________________________________________________
  1              1              CON1                                       RJ45
  2              6              C1,C2,C3,C4,C10,C11             0.1uF
  3              1              C8                                             0.01uF
  4              1              C9                                             1000P 2KV
  5              2              C12,C13                                   27pF
  6              1              D1                                             Dual Color LED
  7              1              D2                                             LED
  8              4              R5,R6,R7,R8                            75
  9              1              R9                                             2.49K 1%
  10            2              R10,R23                                   249
  11            1              R12                                           510
  12            1              R13                                           1K
  13            1              U1                                             GST5009
  14            1              U2                                             RTL8106E Series
  15            1              X1                                             XTAL25M
  Note: This is a R-BOM list for RTL8106E Series.
